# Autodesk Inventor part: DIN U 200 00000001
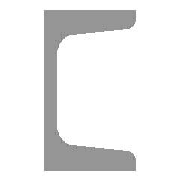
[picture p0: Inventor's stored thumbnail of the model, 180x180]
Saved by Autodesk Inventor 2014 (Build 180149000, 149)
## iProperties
IsCustomPart: 1
Created: 2009-11
Part Number: DIN U 200 00000001
Material: Steel, Mild
Description: U-Shape
Document SubType Name: Modeling
Standard: DIN
Designer: pokornp
Standard Revision: 2000
Standards Organization: DIN
Language: en-US
Size Designation: U 200
Categories: <MemberInstance><Categories><Category DisplayName="Structural Shapes" InternalName="089c4875-fa83-4c05-b084-43b9cc11f5ed" Mnemonic="GRDR"><CategoryParameter Dis
Stock Number: U 200
Density: 7.86 g/cm^3
Appearance: Steel
_CCFamilyMember: 15
_CCFamilyDisplayName: DIN 1026 U - U-Shape
_FrameMemberDoc: Frame Member File
_Version: 15.0.0
G_L: 2500.000 mm
G_W: 75.000 mm
G_H: 200.000 mm
Author: pokornp
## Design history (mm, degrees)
node "Start plane"
node "End plane"
sketch "Sketch"
  geometry: L1 (0, 0)-(0, 100); L2 (0, 100)-(75, 100); L3 (75, 100)-(75, 97.039); L4 (69.478, 91.058)-(19.083, 87.027); L5 (8.5, 75.563)-(8.5, 0); L6 (8.5, 0)-(0, 0); L7 (37.5, 100)-(37.5, 88.5); L8 (75, 91.5)-(75, 88.5); L9 (75, 88.5)-(37.5, 88.5); L10 (0, 15)-(0, -27); L11 (-5.539, 0)-(16.007, 0); L12 (0, 0)-(0, -100); L13 (0, -100)-(75, -100); L14 (75, -100)-(75, -97.039); L15 (69.478, -91.058)-(19.083, -87.027); L16 (8.5, -75.563)-(8.5, 0); L17 (0, 140)-(0, -140) reference; L18 (-21.881, 0)-(92.511, 0) reference; A1 r 11.5 centre (20, 75.563) between (19.083, 87.027) and (8.5, 75.563); A2 r 11.5 centre (20, -75.563) between (8.5, -75.563) and (19.083, -87.027); A3 r 6 centre (69, 97.039) between (69.478, 91.058) and (75, 97.039); A4 r 6 centre (69, -97.039) between (75, -97.039) and (69.478, -91.058); 5 further points
  constraints: 32 end point, 10 point on line, 8 point on circle, 8 tangent, 6 symmetric about line, 4 centre point, 4 parallel, 3 collinear, 3 perpendicular, 2 equal radius, 2 midpoint, 5 other
  dimensions: "d0" = 8.5 distance between parallel lines of L1 L5 (= G_T); "d1" = 100 distance between parallel lines of L6 L2 (= 0.5 x G_H); "d2" = 75 distance between parallel lines of L3 L1 (= G_W); "d3" = 11.5 distance of L2.end L8.end (= G_T1); "d4" = 37.5 distance of L7.start L2.end (= G_C); "d5" = 3 distance of L8.start L8.end (computed from G_NG, G_C); "d23" = 11.5 radius of A1 (= G_IR); "d24" = 6 radius of A3 (= G_ER); "d25" = 0 distance between parallel lines of L10 L12 (computed from ex)
extrude "Body" new body sketch "Sketch" stored distance "d6" = 2500 (= G_L); taper "d7" = 0 deg
node "Driven Length"
  sketch "Sketch3"
    geometry: L1 (0, 0)-(10, 0) reference
    constraints: 2 end point, 1 horizontal
  workplane "Work Plane3"
  sketch "Sketch4"
    geometry: L1 (-2, 0)-(12, 0) reference; L2 (-2, 2500)-(12, 2500) reference
    dimensions: "d29" = 2500 distance between parallel lines of L1 L2 (derived)
body "Solid1"
other parameters: "G_W" = 75 [user parameter; used in 1 equation term], "G_H" = 200 [user parameter; used in 1 equation term], "G_T" = 8.5 [user parameter; used in 1 equation term], "G_T1" = 11.5 [user parameter; used in 1 equation term], "G_NG" = 0.8 [user parameter; used in 1 equation term], "G_ER" = 6 [user parameter; used in 1 equation term], "G_IR" = 11.5 [user parameter; used in 1 equation term], "G_C" = 37.5 [user parameter; used in 2 equation terms], "G_L" = 2500 (= d29) [user parameter; used in 1 equation term], "ex" = 0 [user parameter; used in 1 equation term], "G_OFFSET_START" = 0 [user parameter; used in 1 equation term], "G_OFFSET_END" = 0 [user parameter; used in 1 equation term], "d26" = 0 (computed from G_OFFSET_START), "d28" = 90 deg
